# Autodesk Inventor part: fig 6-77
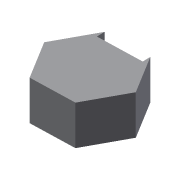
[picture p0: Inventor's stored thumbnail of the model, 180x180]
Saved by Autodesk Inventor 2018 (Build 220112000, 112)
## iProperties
Created: 2009-03
Part Number: fig 6-77
Document SubType Name: Modeling
Designer: Sham
Density: 1 g/cm^3
Material: Generic
Appearance: Default
Author: Sham
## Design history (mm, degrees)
sketch "Sketch5"
  geometry: L1 (-5.929, 9.627)-(5.372, 9.948); L2 (5.372, 9.948)-(11.301, 0.321); L3 (11.301, 0.321)-(5.929, -9.627); L4 (5.929, -9.627)-(-5.372, -9.948); L5 (-5.372, -9.948)-(-11.301, -0.321); L6 (-11.301, -0.321)-(-5.929, 9.627); 1 further point
  constraints: 12 end point, 13 other
extrude "Extrusion3" new body sketch "Sketch5" distance "d13" = 10; taper "d14" = 0 deg
thicken "Thicken2" dims "d15" = 2, "d16" = 2
body "Solid4"
